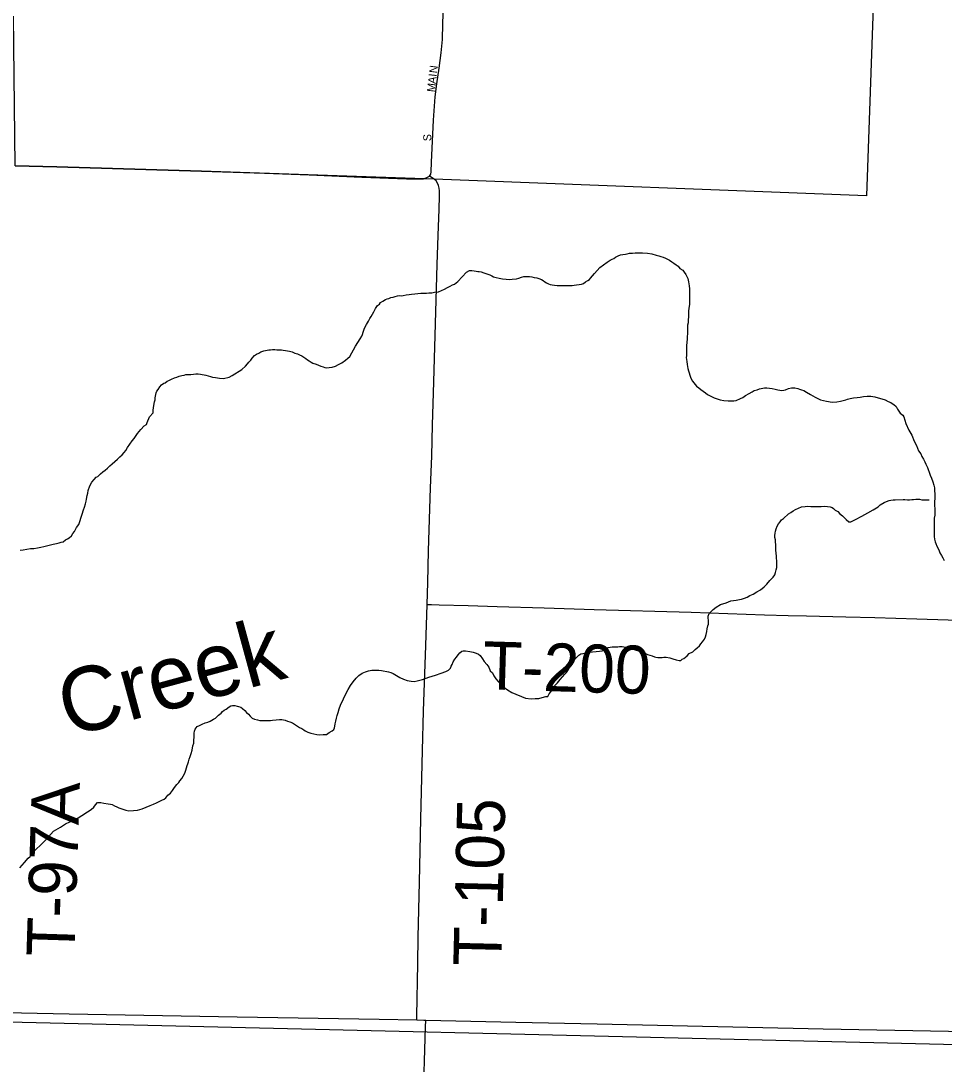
# Model space of a CAD drawing. Extents: x 0 to 64.8, y -5 to 22.
# Drawn here: x 3.652 to 4.744, y 15.77 to 17.005 of the extents above; entities that cross this region are included whole.
import ezdxf

# ---------------------------------------------------------------- set-up
doc = ezdxf.new("R2010")
doc.units = 0
for name, color, linetype in [('GM_X_City_Street', 7, 'Continuous'), ('GM_X_City_Street_Text', 7, 'Continuous'), ('GM_X_Corporation', 7, 'Continuous'), ('GM_X_County_Road', 7, 'Continuous'), ('GM_X_Minor_Lake_Text', 7, 'Continuous'), ('GM_X_Minor_River', 7, 'Continuous'), ('GM_X_Township_Road', 7, 'Continuous'), ('GM_X_Township_Road_Text', 7, 'Continuous')]:
    doc.layers.add(name, color=color, linetype=linetype)

msp = doc.modelspace()

# ---------------------------------------------------------------- linework, layer by layer
at = {"layer": 'GM_X_City_Street'}
msp.add_lwpolyline([(4.1353, 16.8214), (4.1368, 16.8239), (4.1374, 16.8265), (4.1378, 16.838), (4.1403, 16.8875), (4.1423, 16.9153), (4.1439, 16.9307), (4.1467, 16.9491), (4.1493, 16.9675), (4.1508, 16.983), (4.1513, 17.0017), (4.1524, 17.0355), (4.1528, 17.0466), (4.1529, 17.0492), (4.1535, 17.0633), (4.1538, 17.0698), (4.1551, 17.1129), (4.1567, 17.1656), (4.1577, 17.194), (4.1603, 17.2742), (4.1617, 17.3054), (4.1621, 17.3176)], dxfattribs=at)
at = {"layer": 'GM_X_Corporation'}
msp.add_lwpolyline([(4.6701, 17.3022), (4.6523, 16.7981), (4.1411, 16.8179), (3.8657, 16.8272), (3.6946, 16.8325), (3.6455, 16.8336), (3.6435, 17.0108)], dxfattribs=at)
at = {"layer": 'GM_X_County_Road'}
for points in [[(3.6455, 16.8336), (3.6946, 16.8325), (3.8657, 16.8272), (3.9404, 16.8248), (3.9932, 16.8229), (4.0554, 16.8204), (4.1083, 16.8184), (4.1239, 16.8182), (4.1284, 16.8184), (4.1324, 16.8198), (4.1353, 16.8214)], [(3.6146, 15.8319), (3.7091, 15.83), (3.908, 15.8265), (4.0758, 15.8237), (4.1205, 15.8227)], [(4.1013, 14.8145), (4.1014, 14.8184), (4.1015, 14.8276), (4.1031, 14.8896), (4.1081, 15.0448), (4.1111, 15.1441), (4.1134, 15.2247), (4.1201, 15.4543), (4.1232, 15.5598), (4.128, 15.7212), (4.1306, 15.8142), (4.1309, 15.8224)], [(4.1205, 15.8227), (4.1287, 15.8225), (4.1309, 15.8224)], [(4.1309, 15.8224), (4.2374, 15.8201), (4.3338, 15.8181), (4.601, 15.8122), (4.8341, 15.8077), (5.0299, 15.8032), (5.0796, 15.8019), (5.1075, 15.8013), (5.1206, 15.8012)]]:
    msp.add_lwpolyline(points, dxfattribs=at)
at = {"layer": 'GM_X_Minor_River'}
for points in [[(4.165, 16.6937), (4.1689, 16.6967), (4.179, 16.7078), (4.1829, 16.7097), (4.1856, 16.7096), (4.1882, 16.7092), (4.1905, 16.7091), (4.1924, 16.7087), (4.1943, 16.7086), (4.1965, 16.7082), (4.1996, 16.707), (4.2022, 16.7062), (4.2045, 16.7054), (4.2067, 16.7046), (4.209, 16.7034), (4.2112, 16.7022), (4.2143, 16.7014), (4.218, 16.7005), (4.2218, 16.7), (4.226, 16.6996), (4.2298, 16.6991), (4.2332, 16.6994), (4.2382, 16.6997), (4.2412, 16.7007), (4.2443, 16.7018), (4.247, 16.7025), (4.2493, 16.7028), (4.2516, 16.7028), (4.2538, 16.7027), (4.2565, 16.7023), (4.2591, 16.7015), (4.2622, 16.701), (4.2648, 16.7002), (4.2678, 16.699), (4.2697, 16.6978), (4.2719, 16.6963), (4.2738, 16.6951), (4.2761, 16.6939), (4.2783, 16.6931), (4.2806, 16.6926), (4.2833, 16.6922), (4.2863, 16.6921), (4.2897, 16.6921), (4.2931, 16.692), (4.2969, 16.6919), (4.3011, 16.6918), (4.3042, 16.6921), (4.3064, 16.6924), (4.3152, 16.6934), (4.3175, 16.6945), (4.3198, 16.6963), (4.3225, 16.6978), (4.3245, 16.6989), (4.326, 16.7007), (4.3284, 16.7033), (4.3307, 16.7063), (4.3338, 16.7097), (4.337, 16.7134), (4.3412, 16.7164), (4.3455, 16.7197), (4.3493, 16.7219), (4.3516, 16.723), (4.3535, 16.7241), (4.3555, 16.7255), (4.3586, 16.727), (4.3613, 16.7284), (4.3639, 16.7288), (4.3673, 16.7291), (4.3693, 16.7294), (4.3719, 16.7301), (4.3754, 16.7304), (4.3788, 16.7307), (4.383, 16.7306), (4.3875, 16.7305), (4.3932, 16.7304), (4.3982, 16.7295), (4.4034, 16.7279), (4.4065, 16.727), (4.4091, 16.7262), (4.4117, 16.7254), (4.4144, 16.7242), (4.417, 16.723), (4.4193, 16.7218), (4.4219, 16.7199), (4.4245, 16.7183), (4.4271, 16.7163), (4.4294, 16.7148), (4.4316, 16.712), (4.435, 16.7101), (4.4368, 16.7077), (4.4387, 16.705), (4.4398, 16.7027), (4.4408, 16.7001), (4.4419, 16.6962), (4.4425, 16.6917), (4.4428, 16.6879), (4.4431, 16.6833), (4.4428, 16.6696), (4.4423, 16.6651), (4.4419, 16.6617), (4.4418, 16.659)], [(3.8763, 16.5843), (3.8789, 16.5835), (3.8823, 16.5831), (3.8869, 16.5822), (3.8918, 16.5821), (3.8983, 16.5835), (3.9022, 16.5853), (3.9133, 16.5926), (3.9176, 16.5967), (3.9203, 16.5993), (3.9219, 16.6012), (3.9239, 16.6038), (3.9258, 16.606), (3.9285, 16.609), (3.9309, 16.6108), (3.9336, 16.6119), (3.9359, 16.6134), (3.9393, 16.6145), (3.9416, 16.6152), (3.9435, 16.6155), (3.9454, 16.6158), (3.9473, 16.6158), (3.9496, 16.6161), (3.9523, 16.6164), (3.9549, 16.616), (3.958, 16.6159), (3.9603, 16.6159), (3.9625, 16.6155), (3.9652, 16.615), (3.9697, 16.6142), (3.9731, 16.6133), (3.9761, 16.6121), (3.9792, 16.6113), (3.9818, 16.6101), (3.9844, 16.6089), (3.9867, 16.6073), (3.9893, 16.6057), (3.9912, 16.6042), (3.993, 16.603), (3.9953, 16.6014), (3.9975, 16.6002), (4.0013, 16.599), (4.0043, 16.5978), (4.007, 16.5966), (4.0096, 16.5958), (4.0115, 16.595), (4.0138, 16.5945), (4.0168, 16.5949), (4.0203, 16.5955), (4.0241, 16.5966), (4.0279, 16.5984), (4.0318, 16.6006), (4.036, 16.6035), (4.0387, 16.6058), (4.0411, 16.608), (4.0478, 16.62), (4.0506, 16.6245), (4.0533, 16.629), (4.0553, 16.632), (4.0561, 16.6339), (4.0569, 16.6369), (4.0585, 16.6414), (4.0609, 16.6459), (4.0633, 16.6497), (4.0649, 16.653), (4.0665, 16.6553), (4.068, 16.6579), (4.0696, 16.6609), (4.0716, 16.6647), (4.074, 16.6684), (4.0763, 16.6699), (4.0775, 16.6718), (4.0802, 16.6736), (4.0833, 16.6754), (4.0852, 16.6761), (4.0875, 16.6768), (4.0898, 16.6776), (4.0925, 16.6783), (4.0948, 16.679), (4.0974, 16.6797), (4.1001, 16.68), (4.1024, 16.6799), (4.1043, 16.6803), (4.1077, 16.681), (4.1112, 16.6813), (4.1142, 16.6816), (4.118, 16.6822), (4.1218, 16.6825), (4.1253, 16.6828), (4.1283, 16.6828), (4.1317, 16.6831), (4.1348, 16.6834), (4.1382, 16.6833), (4.1413, 16.684), (4.1462, 16.6846), (4.1497, 16.6861), (4.1531, 16.6875), (4.1566, 16.6897), (4.16, 16.6912), (4.1627, 16.6926), (4.165, 16.6937)], [(4.4418, 16.659), (4.4417, 16.6548), (4.4413, 16.6514), (4.4412, 16.648), (4.4407, 16.645), (4.4407, 16.6419), (4.4406, 16.6385), (4.4405, 16.6355), (4.44, 16.6309), (4.44, 16.6283), (4.4399, 16.6249), (4.4394, 16.6207), (4.4394, 16.6184), (4.4393, 16.6165), (4.4393, 16.6139), (4.4392, 16.6116), (4.4392, 16.6089), (4.4391, 16.6066), (4.4394, 16.6044), (4.4398, 16.6021), (4.4401, 16.5986), (4.4404, 16.596), (4.4411, 16.5937), (4.4418, 16.591), (4.4425, 16.5887), (4.4432, 16.586), (4.4443, 16.5837), (4.445, 16.5814), (4.4465, 16.5787), (4.4479, 16.5768), (4.4513, 16.5729), (4.4539, 16.571), (4.4565, 16.569), (4.4591, 16.5671), (4.4617, 16.5651), (4.4644, 16.5631), (4.4674, 16.5616), (4.4696, 16.5604), (4.4723, 16.5592), (4.4756, 16.558), (4.4794, 16.5567), (4.4836, 16.5559), (4.4885, 16.5554), (4.4919, 16.5553), (4.4954, 16.5556), (4.498, 16.5559), (4.5034, 16.5581), (4.5061, 16.5595), (4.5092, 16.5618), (4.5134, 16.5643), (4.5169, 16.5661), (4.5196, 16.5676), (4.523, 16.5687), (4.5257, 16.5697), (4.5276, 16.5701), (4.5295, 16.5704), (4.5318, 16.5707), (4.5345, 16.5707), (4.5375, 16.5706), (4.5409, 16.5702), (4.5443, 16.5693), (4.5474, 16.5685), (4.5496, 16.5681), (4.5519, 16.5676), (4.5546, 16.568), (4.5565, 16.5687), (4.5599, 16.5701), (4.5634, 16.5708), (4.5653, 16.5708), (4.5676, 16.5707), (4.571, 16.5702), (4.5729, 16.5694), (4.5755, 16.5686), (4.5781, 16.5678), (4.5815, 16.5658), (4.586, 16.5631), (4.5917, 16.5599), (4.598, 16.5567), (4.6048, 16.555), (4.6117, 16.5541), (4.6174, 16.5544), (4.6216, 16.555), (4.6246, 16.5557), (4.6277, 16.5568), (4.63, 16.5575), (4.6331, 16.5582), (4.6369, 16.5589), (4.6411, 16.5595), (4.6449, 16.5598), (4.6487, 16.5605), (4.6529, 16.5612), (4.6574, 16.5611), (4.662, 16.5602), (4.6745, 16.5565), (4.6778, 16.5549), (4.6809, 16.5537), (4.6827, 16.5522), (4.6846, 16.551), (4.6872, 16.5486), (4.689, 16.5456), (4.6905, 16.5432)], [(3.6511, 16.3786), (3.6549, 16.3792), (3.6591, 16.3799), (3.6633, 16.3806), (3.6675, 16.3808), (3.6717, 16.3815), (3.6755, 16.3822), (3.6793, 16.3829), (3.6839, 16.3843), (3.6904, 16.3857), (3.6943, 16.3867), (3.6973, 16.3874), (3.6996, 16.3881), (3.7023, 16.3888), (3.705, 16.391), (3.7073, 16.3921), (3.7092, 16.3932), (3.712, 16.3958), (3.7135, 16.3984), (3.7155, 16.4007), (3.7179, 16.4055), (3.7206, 16.4093), (3.7247, 16.4214), (3.726, 16.4266), (3.7275, 16.4296), (3.7284, 16.4334), (3.7292, 16.4368), (3.7297, 16.4391), (3.7305, 16.4436), (3.7313, 16.4463), (3.7318, 16.4493), (3.7338, 16.455), (3.7362, 16.4591), (3.7386, 16.4624), (3.7413, 16.465), (3.7432, 16.4661), (3.7463, 16.4691), (3.749, 16.4713), (3.7517, 16.4735), (3.7544, 16.4758), (3.7572, 16.4784), (3.7599, 16.481), (3.7634, 16.4835), (3.7665, 16.4865), (3.7692, 16.4891), (3.7719, 16.4917), (3.7743, 16.4943), (3.7762, 16.4969), (3.7782, 16.5003), (3.7809, 16.5044), (3.7837, 16.5082), (3.786, 16.5108), (3.79, 16.5168), (3.7939, 16.5216), (3.7978, 16.5261), (3.8005, 16.5275), (3.8013, 16.5298), (3.8041, 16.5366), (3.8084, 16.5414), (3.8085, 16.5445), (3.8094, 16.5501), (3.8102, 16.5543), (3.811, 16.5566), (3.8111, 16.5592), (3.8115, 16.5611), (3.8119, 16.563), (3.8123, 16.5649), (3.8128, 16.5671), (3.8143, 16.569), (3.8163, 16.572), (3.8183, 16.5746), (3.821, 16.5765), (3.8229, 16.5768), (3.8252, 16.5786), (3.8271, 16.5797), (3.8302, 16.5812), (3.8337, 16.5826), (3.8367, 16.5837), (3.8394, 16.5848), (3.8425, 16.5855), (3.8451, 16.5858), (3.8471, 16.5865), (3.8501, 16.5868), (3.8531, 16.5868), (3.8562, 16.5871), (3.8589, 16.5874), (3.8619, 16.5873), (3.8646, 16.5869), (3.8665, 16.5868), (3.8687, 16.5864), (3.871, 16.586), (3.8736, 16.5852), (3.8763, 16.5843)], [(4.6905, 16.5432), (4.692, 16.5409), (4.6953, 16.5386), (4.6964, 16.5366), (4.6989, 16.5286), (4.7022, 16.5209), (4.7058, 16.5148), (4.7087, 16.5079), (4.7116, 16.5025), (4.7138, 16.4964), (4.7164, 16.4929), (4.7178, 16.4898), (4.7196, 16.4864), (4.7211, 16.4833), (4.7225, 16.4806), (4.7236, 16.4783), (4.7244, 16.4764), (4.7254, 16.4741), (4.7265, 16.471), (4.7276, 16.4676), (4.729, 16.4641), (4.7308, 16.4595), (4.7319, 16.4557), (4.7326, 16.4526), (4.7329, 16.4492), (4.7331, 16.445), (4.733, 16.4405), (4.7329, 16.4355), (4.7328, 16.4317), (4.7331, 16.4276), (4.733, 16.4238), (4.733, 16.4203), (4.7325, 16.4165), (4.7324, 16.4131), (4.7324, 16.4105), (4.7323, 16.4074), (4.7322, 16.404), (4.7324, 16.3949), (4.7327, 16.3919), (4.7334, 16.3888), (4.7345, 16.3865), (4.7356, 16.3834), (4.7377, 16.3792), (4.7392, 16.3754), (4.741, 16.3723), (4.7425, 16.3696), (4.7443, 16.3665)], [(4.5445, 16.3911), (4.5438, 16.3938), (4.5438, 16.3961), (4.5443, 16.3988), (4.5447, 16.4014), (4.5455, 16.404), (4.5468, 16.4071), (4.5483, 16.4101), (4.5503, 16.4123), (4.5519, 16.4145), (4.5542, 16.4164), (4.56, 16.4216), (4.5627, 16.4234), (4.5654, 16.4252), (4.5685, 16.4267), (4.5719, 16.4285), (4.5754, 16.43), (4.5796, 16.4306), (4.5827, 16.4309), (4.5864, 16.4305), (4.5906, 16.4304), (4.5944, 16.4303), (4.5986, 16.4306), (4.6024, 16.4309), (4.6062, 16.4304), (4.6092, 16.43), (4.6115, 16.4291), (4.6134, 16.428), (4.6152, 16.426), (4.6182, 16.4244), (4.6208, 16.4217), (4.6238, 16.4194), (4.6261, 16.417), (4.6283, 16.4151), (4.6313, 16.4124), (4.6339, 16.4123), (4.6393, 16.4152), (4.6466, 16.4189), (4.6539, 16.4229), (4.6601, 16.4265), (4.664, 16.4287), (4.6659, 16.4302), (4.6686, 16.4324), (4.6732, 16.435), (4.6759, 16.4364), (4.679, 16.4375), (4.6809, 16.4378), (4.6839, 16.4382), (4.6862, 16.4385), (4.6957, 16.4387), (4.6976, 16.4386), (4.7007, 16.4385), (4.7033, 16.4385), (4.706, 16.4388), (4.7079, 16.4388), (4.7106, 16.4391), (4.7125, 16.439), (4.7148, 16.439), (4.7178, 16.4385), (4.7197, 16.4385), (4.7216, 16.4384), (4.7235, 16.4384), (4.7262, 16.4383), (4.7265, 16.4383)], [(4.3039, 16.2446), (4.3063, 16.248), (4.3086, 16.251), (4.3121, 16.2543), (4.3145, 16.2561), (4.3167, 16.2565), (4.319, 16.2568), (4.3209, 16.2568), (4.3232, 16.2575), (4.3251, 16.2582), (4.3282, 16.2585), (4.3324, 16.2588), (4.3366, 16.2591), (4.3396, 16.2598), (4.3419, 16.2608), (4.3442, 16.2623), (4.3469, 16.2634), (4.3492, 16.2641), (4.3515, 16.2644), (4.3542, 16.2644), (4.3561, 16.2643), (4.358, 16.2643), (4.3603, 16.2646), (4.3633, 16.2649), (4.3671, 16.2641), (4.3735, 16.2624), (4.3799, 16.2604), (4.3845, 16.2591), (4.3879, 16.2572), (4.3909, 16.2563), (4.3931, 16.2551), (4.3962, 16.2543), (4.3988, 16.2535), (4.4014, 16.2527), (4.4033, 16.2522), (4.4056, 16.2518), (4.4079, 16.2518), (4.4105, 16.2517), (4.4125, 16.252), (4.4155, 16.252), (4.4197, 16.2515), (4.4234, 16.2503), (4.4272, 16.2491), (4.4306, 16.2482), (4.4325, 16.2482), (4.4344, 16.2496), (4.4364, 16.2507), (4.4402, 16.2537), (4.4426, 16.2563), (4.4468, 16.2585), (4.4495, 16.2611), (4.4522, 16.2633), (4.4546, 16.2655), (4.4562, 16.2678), (4.4585, 16.2704), (4.4605, 16.2734), (4.4617, 16.276), (4.4625, 16.279), (4.4633, 16.2824), (4.4638, 16.2858), (4.4646, 16.2892), (4.4654, 16.2911), (4.4655, 16.2942), (4.4655, 16.2961), (4.4652, 16.2983), (4.4649, 16.3006), (4.4661, 16.3036), (4.4688, 16.3066), (4.4711, 16.3085), (4.4746, 16.3114), (4.4796, 16.3144), (4.4862, 16.3165), (4.4919, 16.3186), (4.498, 16.3196), (4.5022, 16.3203), (4.5045, 16.3206), (4.5079, 16.3221), (4.511, 16.3231), (4.5145, 16.325), (4.5183, 16.3268), (4.5226, 16.3293), (4.5268, 16.3319), (4.5311, 16.3352), (4.5346, 16.3386), (4.5381, 16.343), (4.542, 16.3468), (4.5439, 16.3494), (4.5448, 16.3524), (4.5456, 16.3554), (4.5464, 16.3581), (4.5461, 16.3603), (4.5461, 16.3634), (4.5462, 16.366), (4.5459, 16.3691), (4.546, 16.3721), (4.5456, 16.3748), (4.545, 16.379), (4.545, 16.382), (4.5451, 16.3851), (4.5448, 16.3885), (4.5445, 16.3911)], [(3.9843, 16.1675), (3.9866, 16.1663), (3.9885, 16.1651), (3.9915, 16.1635), (3.9952, 16.1623), (3.9986, 16.1614), (4.002, 16.1606), (4.0055, 16.1601), (4.0096, 16.1604), (4.0135, 16.1607), (4.0169, 16.1629), (4.0204, 16.1648), (4.0223, 16.1666), (4.0231, 16.1685), (4.0236, 16.1704), (4.024, 16.1734), (4.0245, 16.1764), (4.0253, 16.1798), (4.0261, 16.1832), (4.0273, 16.1866), (4.0286, 16.1908), (4.0302, 16.1953), (4.0338, 16.2028), (4.0366, 16.2088), (4.0394, 16.2137), (4.0421, 16.2186), (4.0453, 16.2231), (4.0488, 16.2272), (4.0519, 16.2305), (4.0558, 16.2331), (4.0596, 16.2349), (4.0634, 16.236), (4.0673, 16.2366), (4.0707, 16.2369), (4.0756, 16.2368), (4.0787, 16.2364), (4.087, 16.2347), (4.0896, 16.2339), (4.0923, 16.2327), (4.0964, 16.2303), (4.1005, 16.2279), (4.1047, 16.2259), (4.1088, 16.2243), (4.1137, 16.2238), (4.1171, 16.2234), (4.121, 16.224), (4.1271, 16.2258), (4.1347, 16.2283), (4.1424, 16.2308), (4.1493, 16.2333), (4.1547, 16.235), (4.1578, 16.2369), (4.1601, 16.2391), (4.1609, 16.2414), (4.1621, 16.2436), (4.1633, 16.2466), (4.1653, 16.2496), (4.1672, 16.2522), (4.1692, 16.2549), (4.1711, 16.2571), (4.1735, 16.2593), (4.1754, 16.2597), (4.178, 16.2596), (4.183, 16.2587), (4.1871, 16.2579), (4.1905, 16.2567), (4.1932, 16.2555), (4.1954, 16.2539), (4.198, 16.25), (4.2002, 16.2469), (4.2031, 16.2435), (4.2054, 16.2404), (4.2072, 16.2358), (4.2098, 16.2334), (4.2116, 16.23), (4.2138, 16.2265), (4.2168, 16.2234), (4.2201, 16.2203), (4.2235, 16.2168), (4.2276, 16.2133), (4.2328, 16.2101), (4.249, 16.2037), (4.2555, 16.2028), (4.2604, 16.203), (4.2646, 16.2033), (4.2688, 16.2044), (4.273, 16.2054), (4.2753, 16.2057), (4.2769, 16.2087), (4.2788, 16.211), (4.2808, 16.214), (4.2832, 16.2181), (4.2867, 16.2218), (4.2898, 16.2255), (4.2929, 16.2289), (4.2953, 16.2319), (4.2976, 16.2341), (4.2992, 16.2364), (4.3008, 16.239), (4.3023, 16.2416), (4.3039, 16.2446)], [(3.7242, 16.0647), (3.7308, 16.0691), (3.7354, 16.072), (3.7385, 16.0746), (3.7405, 16.0772), (3.7428, 16.0802), (3.7466, 16.0801), (3.7504, 16.0793), (3.7553, 16.0784), (3.758, 16.0783), (3.7599, 16.0779), (3.7629, 16.0763), (3.7655, 16.0751), (3.7681, 16.0739), (3.7764, 16.0711), (3.7799, 16.0703), (3.7852, 16.0705), (3.7901, 16.0712), (3.7955, 16.0726), (3.8001, 16.0744), (3.8051, 16.0765), (3.8089, 16.0783), (3.8124, 16.0798), (3.8158, 16.0812), (3.8189, 16.0827), (3.8216, 16.0841), (3.8235, 16.0856), (3.8259, 16.0886), (3.829, 16.0912), (3.8314, 16.0945), (3.8337, 16.0979), (3.8364, 16.1013), (3.8388, 16.1039), (3.8403, 16.1057), (3.8423, 16.1084), (3.8439, 16.1114), (3.8455, 16.114), (3.8463, 16.1162), (3.8471, 16.1185), (3.8479, 16.1211), (3.8487, 16.1238), (3.8496, 16.126), (3.8504, 16.1283), (3.8512, 16.1313), (3.8524, 16.1347), (3.8536, 16.1381), (3.8545, 16.1419), (3.8554, 16.1472), (3.8566, 16.1502), (3.8566, 16.1525), (3.8567, 16.1548), (3.8571, 16.1566), (3.8572, 16.1601), (3.8572, 16.1623), (3.8573, 16.1646), (3.8581, 16.1669), (3.8608, 16.1702), (3.8635, 16.1713), (3.8666, 16.1728), (3.87, 16.1742), (3.8731, 16.1753), (3.8758, 16.1764), (3.8781, 16.1774), (3.88, 16.1789), (3.8823, 16.18), (3.8858, 16.1833), (3.8889, 16.1859), (3.8905, 16.1878), (3.8924, 16.1893), (3.8951, 16.1907), (3.8986, 16.1933), (3.9005, 16.1944), (3.9025, 16.1951), (3.9051, 16.1951), (3.9078, 16.1943), (3.9096, 16.1938), (3.9123, 16.193), (3.9142, 16.1914), (3.9168, 16.1891), (3.919, 16.1868), (3.9212, 16.1845), (3.9231, 16.1821), (3.9257, 16.1798), (3.9283, 16.1786), (3.9321, 16.1778), (3.9347, 16.1773), (3.9378, 16.1772), (3.9412, 16.1772), (3.9473, 16.177), (3.9496, 16.1777), (3.9542, 16.178), (3.958, 16.1783), (3.9606, 16.1782), (3.9648, 16.1774), (3.9674, 16.1762), (3.9704, 16.1754), (3.9735, 16.1742), (3.9757, 16.173), (3.978, 16.1714), (3.9817, 16.169), (3.9843, 16.1675)], [(3.6509, 16.0029), (3.6564, 16.0092), (3.6607, 16.0141), (3.663, 16.0163), (3.6642, 16.0185), (3.6666, 16.0215), (3.6705, 16.0252), (3.6751, 16.0293), (3.6798, 16.0341), (3.6849, 16.0393), (3.6907, 16.046), (3.6988, 16.0508), (3.705, 16.0548), (3.71, 16.0574), (3.713, 16.0581), (3.7161, 16.0599), (3.72, 16.0621), (3.7242, 16.0647)], [(3.4389, 15.8253), (4.859, 15.7914)]]:
    msp.add_lwpolyline(points, dxfattribs=at)
at = {"layer": 'GM_X_Township_Road'}
for points in [[(4.1326, 16.3146), (4.1334, 16.3406), (4.1344, 16.3779), (4.1367, 16.4525), (4.1381, 16.4899), (4.139, 16.5272), (4.1402, 16.5645), (4.1421, 16.6329), (4.1445, 16.7169), (4.1456, 16.7511), (4.1469, 16.7822), (4.1474, 16.7978), (4.1471, 16.804), (4.1467, 16.8071), (4.146, 16.8102), (4.1449, 16.813), (4.1433, 16.8157), (4.1411, 16.8179), (4.1353, 16.8214)], [(4.1205, 15.8227), (4.1206, 15.8272), (4.1218, 15.8895), (4.1221, 15.9206), (4.1235, 15.9859), (4.1253, 16.0606), (4.1273, 16.1415), (4.1285, 16.1882), (4.1309, 16.2659), (4.1326, 16.3146)], [(4.1326, 16.3146), (4.1377, 16.3144), (4.147, 16.314), (4.1811, 16.3133), (4.2153, 16.3122), (4.2711, 16.3105), (4.33, 16.3085), (4.4449, 16.3052), (4.5317, 16.3024), (4.5596, 16.3015), (4.5814, 16.3009), (4.6279, 16.2997), (4.662, 16.2989), (4.7117, 16.2974), (4.7489, 16.2962), (4.7923, 16.295), (4.842, 16.2942), (4.8855, 16.293), (4.9196, 16.2921), (4.9941, 16.2906), (5.0592, 16.2892), (5.1217, 16.2874), (5.1315, 16.2869), (5.1372, 16.2867)]]:
    msp.add_lwpolyline(points, dxfattribs=at)

# ---------------------------------------------------------------- texts
at = {"layer": 'GM_X_City_Street_Text'}
for s, rotation, p in [('I', 83.4518, (4.1437, 16.9387)), ('N', 82.7394, (4.1442, 16.9428)), ('M', 83.4511, (4.1416, 16.9205)), ('A', 83.4517, (4.1428, 16.9304)), ('S', 90, (4.1375, 16.8628))]:
    msp.add_text(s, height=0.00947, rotation=rotation, dxfattribs=at).set_placement(p)
at = {"layer": 'GM_X_Minor_Lake_Text'}
msp.add_text('Creek', height=0.0758, rotation=15.2045, dxfattribs=at).set_placement((3.7084, 16.1571))
at = {"layer": 'GM_X_Township_Road_Text'}
for s, rotation, p in [('T-200', 358.3163, (4.1978, 16.2142)), ('T-97A', 88.1942, (3.7154, 15.8969)), ('T-105', 88.6102, (4.2203, 15.886))]:
    msp.add_text(s, height=0.05682, rotation=rotation, dxfattribs=at).set_placement(p)

doc.saveas('drawing.dxf')
